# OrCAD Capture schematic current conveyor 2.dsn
size A
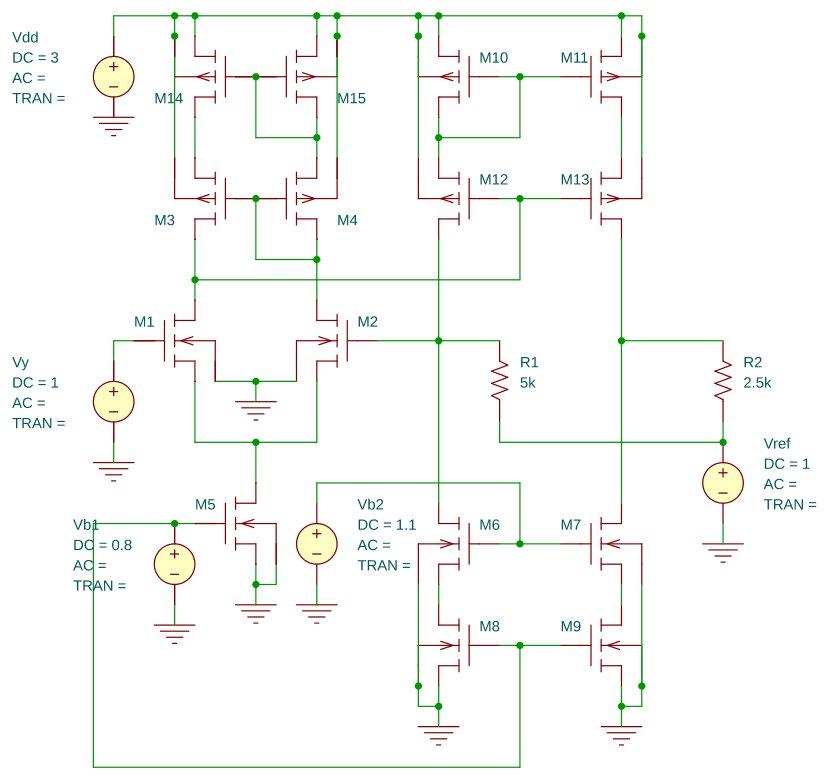
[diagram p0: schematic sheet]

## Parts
M1  MbreakN
M2  MbreakN
M3  MbreakP
M4  MbreakP
M5  MbreakN
M6  MbreakN
M7  MbreakN
M8  MbreakN
M9  MbreakN
M10  MbreakP
M11  MbreakP
M12  MbreakP
M13  MbreakP
M14  MbreakP
M15  MbreakP
R1  5k  [AX/RC05]
R2  2.5k  [AX/RC05]
Vb1  VSRC
Vb2  VSRC
Vdd  VSRC
Vref  VSRC
Vy  VSRC

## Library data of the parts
M1 M2 = MbreakN: L: 0.35u; W: 70u
M3 M4 M14 M15 = MbreakP: L: 0.7u; W: 100u
M5 = MbreakN: L: 0.7u; W: 14u
M6 M7 = MbreakN: L: 0.7u; W: 140u
M8 M9 = MbreakN: L: 0.7u; W: 50u
M10-M13 = MbreakP: L: 0.7u; W: 420u
R1 R2 = R
Vb1 = VSRC: DC: 0.8
Vb2 = VSRC: DC: 1.1
Vdd = VSRC: DC: 3
Vref Vy = VSRC: DC: 1

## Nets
0: M1.4(b) M2.4(b) M5.0(s) M5.4(b) M6.4(b) M7.4(b) M8.0(s) M8.4(b) M9.0(s) M9.4(b) Vb1.1(-) Vb2.1(-) Vdd.1(-) Vref.1(-) Vy.1(-)
N00211: M1.0(s) M2.0(s) M5.2(d)
N00290: M2.2(d) M3.0(g) M4.0(g) M4.2(d)
N00325: M1.2(d) M3.2(d) M12.0(g) M13.0(g)
N00491: M3.4(b) M4.4(b) M10.1(s) M10.4(b) M11.1(s) M11.4(b) M12.4(b) M13.4(b) M14.1(s) M14.4(b) M15.1(s) M15.4(b) Vdd.0(+)
N00539: M4.1(s) M14.0(g) M15.0(g) M15.2(d)
N00564: M3.1(s) M14.2(d)
N01146: M7.0(s) M9.2(d)
N01241: M1.1(g) Vy.0(+)
N01321: M7.2(d) M13.2(d) R2.2
N01426: M5.1(g) M8.1(g) M9.1(g) Vb1.0(+)
N06776: M11.2(d) M13.1(s)
N08840: M2.1(g) M6.2(d) M12.2(d) R1.2
N09234: M6.1(g) M7.1(g) Vb2.0(+)
N10667: M6.0(s) M8.2(d)
N11255: M10.0(g) M10.2(d) M11.0(g) M12.1(s)
N18908: R1.1 R2.1 Vref.0(+)
